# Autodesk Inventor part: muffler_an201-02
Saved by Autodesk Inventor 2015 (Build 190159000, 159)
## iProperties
Created: 2018-08
Part Number: muffler_an201-02
Checked By: TraceParts S.A.
Material: Generic
Catalog Web Link: www.traceparts.com
Document SubType Name: Modeling
Designer: TraceParts
Density: 1 g/cm^3
Appearance: Default
Company: TraceParts S.A.
Author: TraceParts
REFERENCE: AN201-02
DESIGN: MufflerAN201-02
SUPPLIER: ZheJiang XingChen pneumatic Co., LTD
TraceParts.PartNumber: 50-17072015-115205
TraceParts.PartTitle: Muffler
TraceParts.InstanceId: 50-17072015-115205657ZW2ZC35MUSW16B02ISXHZE
TraceParts.PartStatus: Published
TraceParts.PartVersion: 1.1.1
TRACEPARTS: TRACEPARTS
TraceParts.PartLanguage: en
TraceParts.ClassPath: XINGCHEN_PNEUMATIC:50-17072015-115205
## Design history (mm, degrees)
feature "muffler_an201-02"
body "Solid1"
